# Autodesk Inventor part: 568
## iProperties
Author: Administrator
Shininess: 64.0
Angle Display Precision: 2
Document Length Units: 11272
Document Angle Units: 11286
Document Time Units: 11279
Document Mass Units: 11290
Document Length Units Precision: 3
Document Angle Units Precision: 2
Compacted: True
PropertySet Name: _Private Model Information
Created: 2002-03
Part Number: 568
Material: Stainless Steel, 440C
Document SubType Name: Modeling
Designer: Administrator
Control State: 0
Master: False
Checked Out: False
PropertySet Name: Design Tracking Control
Density: 0.0
Volumn: 0.0
Area: 0.0
PropertySet Name: Model Information
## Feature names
1. Revolution1
